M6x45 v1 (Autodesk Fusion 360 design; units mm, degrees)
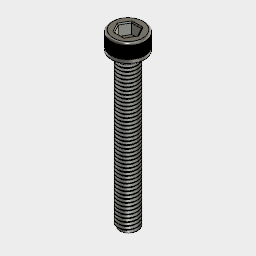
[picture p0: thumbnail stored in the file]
sketch "スケッチ1"
  circle C1 centre (0, 0) radius 3
  circle C2 centre (0, 0) radius 5
  dimension "d1" diameter C1 = 6
  dimension "d2" diameter C2 = 10
extrude "押し出し1" new body sketch "スケッチ1" blind 5.8
sketch "スケッチ2" plane through (0, 0, 5.8) normal (0, 0, 1) x axis (-1, 0, 0)
  line L1 (-1.4722, -2.55) -> (-2.9445, 0)
  line L2 (1.4722, -2.55) -> (-1.4722, -2.55)
  line L3 (2.9445, 0) -> (1.4722, -2.55)
  line L4 (1.4722, 2.55) -> (2.9445, 0)
  line L5 (-1.4722, 2.55) -> (1.4722, 2.55)
  line L6 (-2.9445, 0) -> (-1.4722, 2.55)
  circle C1 centre (0, 0) radius 5
  dimension "d5" distance L2 L5 = 5.1
work_plane "作業平面" sketch "スケッチ2" AlongDistance -0.75
extrude "押し出し2" cut sketch "スケッチ2" profile of L1 L2 L3 L4 L5 L6 against normal blind 3.3
chamfer "面取り" distance 0.3
sketch "スケッチ3" plane through (0, 0, 5.05) normal (0, 0, 1) x axis (1, 0, 0)
  line L1 (-0.05, 4.9497) -> (-0.05, 4.9997)
  line L2 (0.05, 4.9497) -> (-0.05, 4.9497)
  line L3 (0.05, 4.9997) -> (0.05, 4.9497)
  circle C1 centre (0, 0) radius 5
  point P4 (-0.05, 4.9497)
  point P5 (0.05, 4.9497)
  point P3 (-0.05, 4.9997)
  point P6 (0.05, 4.9997)
  dimension "d18" distance P4 P5 = 0.1
  dimension "d19" distance P3 P4 = 0.05
  dimension "d20" distance P5 P6 = 0.05 (= "d19")
extrude "押し出し3" cut sketch "スケッチ3" against normal blind 3.6
work_axis "作業軸"
circular_pattern "C パターン" countU 100 TotalAngle 360
fillet "フィレット1" radius 0.6
extrude "押し出し4" add sketch "スケッチ1" profile of C1 blind -45
thread "ねじ"
fillet "フィレット2" sketch "スケッチ3" radius 0.5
